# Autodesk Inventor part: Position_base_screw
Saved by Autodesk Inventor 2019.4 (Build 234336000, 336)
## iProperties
Created: 2019-10
Part Number: Position_base_screw
Material: Generic
Document SubType Name: Modeling
Designer: Administrator
Density: 1 g/cm^3
Appearance: Default
Title: Position_base_screw
Author: Administrator
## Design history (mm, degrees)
feature "Body1"
feature "Body2"
body "Solid1"
body "Solid2"
